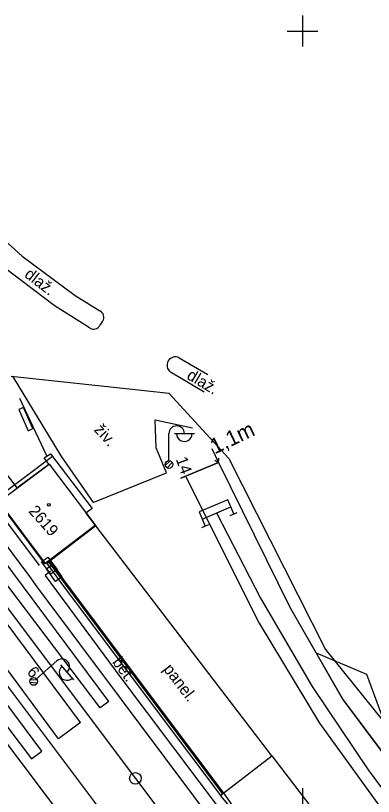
# Model space of a CAD drawing. Extents: x -804166 to -803706, y -1151030 to -1150147.
# Drawn here: x -804037.2 to -803990.8, y -1150299.1 to -1150198 of the extents above; entities that cross this region are included whole.
import ezdxf

# ---------------------------------------------------------------- set-up
doc = ezdxf.new("R2010")
doc.units = 0
for name, color, linetype in [('0381KM032-037P - Vrstva 1', 7, 'Continuous'), ('0381KM032-037P - Vrstva 13', 7, 'Continuous'), ('0381KM032-037P - Vrstva 14', 7, 'Continuous'), ('0381KM032-037P - Vrstva 15', 7, 'Continuous'), ('0381KM032-037P - Vrstva 16', 7, 'Continuous'), ('0381KM032-037P - Vrstva 17', 7, 'Continuous'), ('0381KM032-037P - Vrstva 23', 7, 'Continuous'), ('0381KM032-037P - Vrstva 25', 7, 'Continuous'), ('0381KM032-037P - Vrstva 33', 7, 'Continuous'), ('0381KM032-037P - Vrstva 4', 7, 'Continuous'), ('0381KM032-037P - Vrstva 49', 7, 'Continuous'), ('0381KM032-037P - Vrstva 51', 7, 'Continuous'), ('0381KM032-037P - Vrstva 55', 7, 'Continuous'), ('0381KM032-037P - Vrstva 57', 7, 'Continuous'), ('0381KM032-037P - Vrstva 59', 7, 'Continuous'), ('0381KM032-037P - Vrstva 7', 7, 'Continuous'), ('hran DP - hran DP', 7, 'Continuous'), ('krizky_1000 - Vrstva 1', 7, 'Continuous')]:
    doc.layers.add(name, color=color, linetype=linetype)

msp = doc.modelspace()

# ---------------------------------------------------------------- linework, layer by layer
at = {"layer": '0381KM032-037P - Vrstva 1'}
for points in [[(-804087.93, -1150205.28), (-804078.71, -1150215.28), (-804072.37, -1150222.52), (-804072.08, -1150222.85), (-804071.47, -1150223.58), (-804065.48, -1150230.82), (-804059.47, -1150238.51), (-804055.55, -1150243.68), (-804054.36, -1150245.27), (-804043.89, -1150259.22), (-804035.37, -1150270.61), (-804034.4, -1150271.93), (-804017.97, -1150293.92), (-804002.6, -1150314.46), (-803985.38, -1150337.43), (-803955.87, -1150376.72)], [(-804089.35, -1150206.44), (-804078.67, -1150220.7), (-804069.15, -1150233.38), (-804067.86, -1150235.11), (-804059.28, -1150246.53), (-804058.07, -1150248.16), (-804048.7, -1150260.65), (-804037.85, -1150275.13), (-804021.63, -1150296.76), (-804006.14, -1150317.34), (-803988.98, -1150340.29), (-803981.9, -1150349.73)], [(-804090.39, -1150214.38), (-804086.65, -1150219.55), (-804073.82, -1150237.11), (-804072.56, -1150238.83), (-804064.05, -1150250.31), (-804062.81, -1150251.97), (-804052.29, -1150266.05), (-804042.5, -1150279.11), (-804026.55, -1150300.33), (-804011.27, -1150320.63), (-803993.37, -1150344.49), (-803965.17, -1150382.07), (-803953.84, -1150397.19)], [(-804093.97, -1150217.42), (-804088.17, -1150225.67), (-804077.51, -1150240.28), (-804068.52, -1150252.21), (-804067.31, -1150253.81), (-804055.01, -1150270.12), (-804046.09, -1150281.93), (-804030.05, -1150303.21), (-804014.76, -1150323.52), (-803996.92, -1150347.35), (-803968.88, -1150385.42), (-803942.6, -1150419.03)], [(-804011.14, -1150262.39), (-804005.45, -1150273.41), (-803998.73, -1150284.85), (-803991.51, -1150295.63), (-803978.8, -1150312.77), (-803963.69, -1150332.99), (-803952.21, -1150348.36), (-803946.3, -1150356.39), (-803941.6, -1150363.14), (-803936.71, -1150370.83), (-803932.05, -1150378.84), (-803927.78, -1150386.91), (-803924.06, -1150395.18), (-803920.62, -1150403.65), (-803918.06, -1150410.86), (-803915.07, -1150420.32), (-803912.96, -1150427.25), (-803910.49, -1150435.34), (-803907.33, -1150445.05), (-803903.67, -1150454.38), (-803897.94, -1150464.6), (-803891.97, -1150476.6)]]:
    msp.add_lwpolyline(points, dxfattribs=at)
at = {"layer": '0381KM032-037P - Vrstva 13'}
for p, q in [((-804011.73, -1150254.06), (-804010.87, -1150255.86)), ((-804032.73, -1150268.64), (-804030.94, -1150271.03)), ((-804030.94, -1150271.03), (-804018.44, -1150287.75)), ((-804018.44, -1150287.75), (-804010.19, -1150298.7)), ((-804010.19, -1150298.7), (-804007.43, -1150302.56))]:
    msp.add_line(p, q, dxfattribs=at)
for points in [[(-804011.36, -1150255.54), (-804010.87, -1150255.86), (-804010.82, -1150255.28)], [(-804010.87, -1150255.86), (-804015.74, -1150257.89), (-804015.74, -1150257.89), (-804010.87, -1150255.86)]]:
    msp.add_lwpolyline(points, dxfattribs=at)
at = {"layer": '0381KM032-037P - Vrstva 14'}
for p, q in [((-804028.77, -1150289.52), (-804076.45, -1150225.31)), ((-804031.59, -1150291.62), (-804079.27, -1150227.4)), ((-804033.77, -1150293.24), (-804081.46, -1150229.02)), ((-804083.37, -1150230.42), (-804035.09, -1150294.23)), ((-804025.08, -1150286.79), (-804026.2, -1150287.61)), ((-804028.77, -1150289.52), (-804031.59, -1150291.62)), ((-804035.09, -1150294.23), (-804033.77, -1150293.24))]:
    msp.add_line(p, q, dxfattribs=at)
for points in [[(-804026.2, -1150287.61), (-804040.5, -1150268.78), (-804056.56, -1150247.39), (-804058.99, -1150244.12), (-804066.4, -1150234.12), (-804074.2, -1150223.73)], [(-804025.08, -1150286.79), (-804066.44, -1150231.31), (-804073.38, -1150223.27)]]:
    msp.add_lwpolyline(points, dxfattribs=at)
at = {"layer": '0381KM032-037P - Vrstva 15'}
for p, q in [((-804012.98, -1150263.18), (-804009.3, -1150261.6)), ((-804009.37, -1150262.72), (-804008.45, -1150262.33)), ((-804013.05, -1150264.29), (-804012.13, -1150263.9))]:
    msp.add_line(p, q, dxfattribs=at)
msp.add_lwpolyline([(-804008.91, -1150262.52), (-804009.69, -1150260.68), (-804013.37, -1150262.26), (-804012.59, -1150264.1)], dxfattribs=at)
at = {"layer": '0381KM032-037P - Vrstva 16'}
for p, q in [((-804026.77, -1150264.06), (-804032.89, -1150268.75)), ((-804003.99, -1150293.85), (-804026.77, -1150264.06)), ((-804033.12, -1150268.93), (-804032.89, -1150268.75)), ((-804018.6, -1150287.79), (-804010.38, -1150298.76)), ((-804018.83, -1150288.05), (-804010.58, -1150299)), ((-804010.38, -1150298.76), (-804003.99, -1150293.85)), ((-804010.58, -1150299), (-804010.38, -1150298.76))]:
    msp.add_line(p, q, dxfattribs=at)
for points in [[(-804033.12, -1150268.93), (-804031.33, -1150271.33), (-804018.83, -1150288.05)], [(-804032.89, -1150268.75), (-804031.1, -1150271.13), (-804018.6, -1150287.79)], [(-804032.64, -1150269.93), (-804033.34, -1150270.47), (-804023.51, -1150283.74), (-804006.75, -1150306.05), (-804006.63, -1150306.04)], [(-804003.99, -1150293.85), (-803995.7, -1150304.68), (-804002.75, -1150311.23), (-804006.63, -1150306.04), (-804005.86, -1150304.94), (-804007.53, -1150302.64), (-804010.58, -1150299)]]:
    msp.add_lwpolyline(points, dxfattribs=at)
at = {"layer": '0381KM032-037P - Vrstva 17'}
msp.add_line((-804033.09, -1150255.01), (-804036.6, -1150247.55), dxfattribs=at)
at = {"layer": '0381KM032-037P - Vrstva 23'}
for points in [[(-804034.08, -1150269.19), (-804040.27, -1150260.96), (-804032.39, -1150255.05)], [(-804039.34, -1150260.91), (-804032.82, -1150256.05), (-804026.77, -1150264.06)], [(-804026.77, -1150264.06), (-804033.29, -1150268.94), (-804039.34, -1150260.91)]]:
    msp.add_lwpolyline(points, dxfattribs=at)
at = {"layer": '0381KM032-037P - Vrstva 25'}
for p, q in [((-804017.3, -1150255.61), (-804017.3, -1150252.11)), ((-804016.59, -1150252.11), (-804013.99, -1150252.11)), ((-804017.77, -1150256.26), (-804017.15, -1150255.64)), ((-804017.53, -1150256.55), (-804016.86, -1150255.87)), ((-804034.45, -1150283.87), (-804031.83, -1150281.54)), ((-804031.36, -1150282.07), (-804029.64, -1150284.01)), ((-804035.31, -1150284.31), (-804034.35, -1150284.37)), ((-804035.25, -1150283.94), (-804034.37, -1150283.99))]:
    msp.add_line(p, q, dxfattribs=at)
for points in [[(-804033.78, -1150268.7), (-804032.98, -1150268.1), (-804031.79, -1150269.72), (-804032.6, -1150270.31), (-804033.78, -1150268.7)], [(-804033.14, -1150269.61), (-804032.33, -1150269.03), (-804031.17, -1150270.66), (-804031.98, -1150271.24), (-804033.14, -1150269.61)]]:
    msp.add_lwpolyline(points, dxfattribs=at)
for centre in [(-804017.3, -1150256.11), (-804017.3, -1150256.11), (-804034.82, -1150284.2), (-804034.82, -1150284.2)]:
    msp.add_circle(centre, 0.5, dxfattribs=at)
for centre, start, end in [((-804016.3, -1150252.11), 0, 180), ((-804015.3, -1150252.13), 179.2974, 0.7026), ((-804031.17, -1150282.29), 311.5784, 131.5784), ((-804030.51, -1150283.05), 130.8758, 312.281)]:
    msp.add_arc(centre, 1, start, end, dxfattribs=at)
at = {"layer": '0381KM032-037P - Vrstva 33'}
msp.add_lwpolyline([(-804035.53, -1150251.74), (-804034.92, -1150251.47), (-804036.13, -1150248.73), (-804036.75, -1150249.01)], close=True, dxfattribs=at)
at = {"layer": '0381KM032-037P - Vrstva 4'}
for points in [[(-804015.09, -1150257.7), (-804005.61, -1150276.65), (-803997.81, -1150289.61), (-803985.99, -1150305.97), (-803963.83, -1150335.54), (-803947.69, -1150357.39), (-803941.6, -1150366.02), (-803933.49, -1150379.54), (-803925.57, -1150395.83), (-803919.57, -1150411.36), (-803915.11, -1150425.7)], [(-804033.34, -1150270.47), (-804023.51, -1150283.74), (-804006.75, -1150306.05), (-804002.75, -1150311.23), (-803984.52, -1150335.59), (-803962.04, -1150365.45)]]:
    msp.add_lwpolyline(points, dxfattribs=at)
at = {"layer": '0381KM032-037P - Vrstva 49'}
for points in [[(-804010.87, -1150255.86), (-804001.61, -1150274.67), (-803994.7, -1150286.68), (-803981.46, -1150304.36), (-803936.05, -1150366.09), (-803921.77, -1150392.54), (-803912.22, -1150419.28), (-803908.81, -1150430.91)], [(-804010.87, -1150255.86), (-804010.87, -1150255.86), (-804001.65, -1150274.6), (-803994.86, -1150286.39), (-803989.31, -1150293.81), (-803989.41, -1150293.74)], [(-803998.25, -1150280.5), (-803991.69, -1150283.27), (-803989.47, -1150289.34)]]:
    msp.add_lwpolyline(points, dxfattribs=at)
at = {"layer": '0381KM032-037P - Vrstva 51'}
for p, q in [((-804025.88, -1150237.56), (-804026.25, -1150238.06)), ((-804015.96, -1150242.31), (-804012.26, -1150244.47)), ((-804012.73, -1150246.76), (-804017.09, -1150244.14))]:
    msp.add_line(p, q, dxfattribs=at)
for points in [[(-804044.22, -1150222.03), (-804036.31, -1150229.15), (-804029.46, -1150234.23), (-804026.23, -1150236.21)], [(-804027.57, -1150238.43), (-804032.18, -1150235.55), (-804038.4, -1150230.77), (-804045.96, -1150223.83), (-804046.63, -1150224.5), (-804046.89, -1150224.2)], [(-804037.56, -1150244.69), (-804031.31, -1150254.99), (-804027.1, -1150261.05), (-804017.62, -1150257.21), (-804018.95, -1150253.97), (-804019.08, -1150250.33), (-804014.25, -1150251.35)], [(-804015.09, -1150257.7), (-804005.61, -1150276.65), (-803997.81, -1150289.61), (-803985.99, -1150305.97), (-803963.83, -1150335.54), (-803947.69, -1150357.39), (-803941.6, -1150366.02), (-803933.49, -1150379.54), (-803925.57, -1150395.83), (-803919.57, -1150411.36), (-803915.11, -1150425.7)]]:
    msp.add_lwpolyline(points, dxfattribs=at)
for centre, major_axis, ratio, start_param, end_param in [((-804026.69, -1150237.05), (0.085, 0.955), 0.999815, 4.242277, 5.86844), ((-804027.06, -1150237.72), (-0.618, -0.618), 0.999716, 0.15876, 1.957098), ((-804016.46, -1150243.27), (-0.422, -0.994), 0.999309, 3.06867, 6.055029)]:
    msp.add_ellipse(centre, major_axis=major_axis, ratio=ratio, start_param=start_param, end_param=end_param, dxfattribs=at)
at = {"layer": '0381KM032-037P - Vrstva 55'}
msp.add_lwpolyline([(-804042.49, -1150256.99), (-804040.01, -1150255.2), (-804037.01, -1150259.13), (-804032.83, -1150256.09), (-804033.46, -1150255.26), (-804032.63, -1150254.75), (-804027.25, -1150261.82), (-804028.04, -1150262.42), (-804026.84, -1150264.01), (-804033.36, -1150268.97), (-804039.39, -1150261.01)], close=True, dxfattribs=at)
at = {"layer": '0381KM032-037P - Vrstva 59'}
msp.add_circle((-804032.85, -1150261.34), 0.175, dxfattribs=at)
at = {"layer": '0381KM032-037P - Vrstva 7'}
msp.add_circle((-804021.64, -1150296.75), 0.75, dxfattribs=at)
at = {"layer": 'hran DP - hran DP'}
for p, q in [((-804037.73, -1150244.68), (-804020.87, -1150246.51)), ((-804020.87, -1150246.51), (-804017.32, -1150246.9)), ((-804017.32, -1150246.9), (-804009.55, -1150255.32)), ((-804009.55, -1150255.32), (-803997.02, -1150280.06)), ((-803997.02, -1150280.06), (-803982.8, -1150297.76))]:
    msp.add_line(p, q, dxfattribs=at)
at = {"layer": 'krizky_1000 - Vrstva 1'}
for points in [[(-804000, -1150198), (-804000, -1150202)], [(-804002, -1150200), (-803998, -1150200)], [(-804000, -1150298), (-804000, -1150302)]]:
    msp.add_lwpolyline(points, dxfattribs=at)

# ---------------------------------------------------------------- texts
at = {"layer": '0381KM032-037P - Vrstva 13'}
msp.add_text('1,1m', height=2, rotation=25.39, dxfattribs=at).set_placement((-804011.36, -1150254.81))
at = {"layer": '0381KM032-037P - Vrstva 16'}
for s, rotation, p in [('bet.', 306.5425, (-804024.71, -1150281.72)), ('panel.', 307.3989, (-804018.1, -1150282.62))]:
    msp.add_text(s, height=1.5, rotation=rotation, dxfattribs=at).set_placement(p)
at = {"layer": '0381KM032-037P - Vrstva 25'}
for s, rotation, p in [('14', 290, (-804016.43, -1150255.42)), ('6', 311.5784, (-804035.78, -1150283.05))]:
    msp.add_text(s, height=1.5, rotation=rotation, dxfattribs=at).set_placement(p)
at = {"layer": '0381KM032-037P - Vrstva 51'}
for s, rotation, p in [('dlaž.', 322.4479, (-804036.12, -1150231.74)), ('dlaž.', 328.9976, (-804015.11, -1150244.94)), ('živ.', 312.047, (-804027.08, -1150251.68))]:
    msp.add_text(s, height=1.5, rotation=rotation, dxfattribs=at).set_placement(p)
at = {"layer": '0381KM032-037P - Vrstva 57'}
msp.add_text('2619', height=1.5, rotation=311.6073, dxfattribs=at).set_placement((-804035.56, -1150262.21))

doc.saveas('drawing.dxf')
